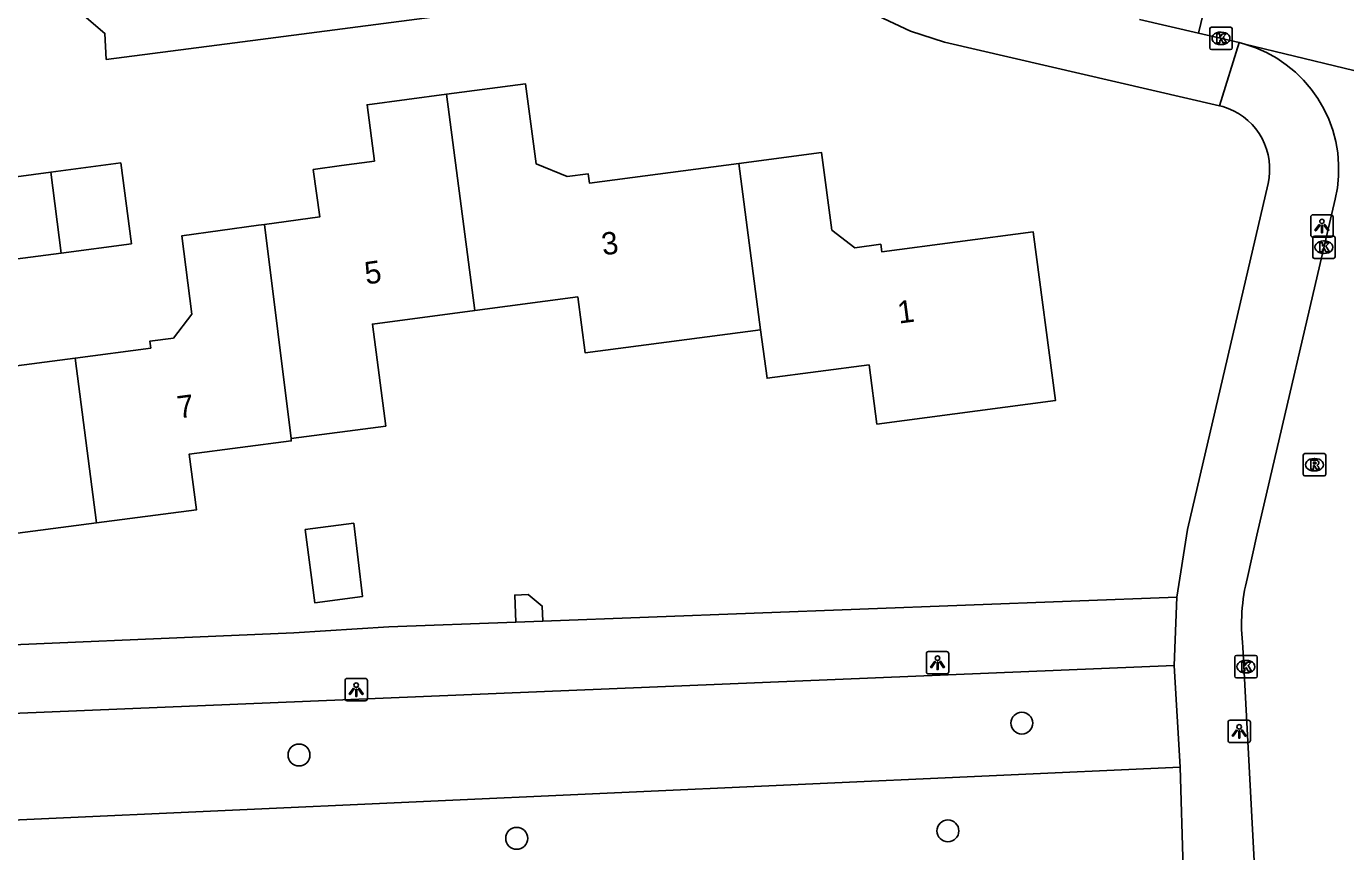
# Model space of a CAD drawing. Extents: x 161084 to 161928, y 385355 to 386522.
# Drawn here: x 161226.8 to 161285.7, y 385835.6 to 385872.4 of the extents above; entities that cross this region are included whole.
import ezdxf

# ---------------------------------------------------------------- set-up
doc = ezdxf.new("R2010")
doc.units = 0
for name, color, linetype in [('IMGEO_Boom', 7, 'Continuous'), ('IMGEO_Groenvoorziening', 7, 'Continuous'), ('IMGEO_Kolk', 7, 'Continuous'), ('IMGEO_Lichtpunt', 7, 'Continuous'), ('IMGEO_Muur', 7, 'Continuous'), ('IMGEO_Pand', 7, 'Continuous'), ('IMGEO_Pand_nummerreeks', 7, 'Continuous'), ('IMGEO_Rijbaan_lokaal_open', 7, 'Continuous'), ('IMGEO_Rioolput', 7, 'Continuous'), ('IMGEO_Voetpad_open', 7, 'Continuous')]:
    doc.layers.add(name, color=color, linetype=linetype)

msp = doc.modelspace()

# ---------------------------------------------------------------- linework, layer by layer
at = {"layer": 'IMGEO_Boom'}
for centre in [(161271.206, 385841.322), (161238.934, 385839.897), (161267.906, 385836.508), (161248.656, 385836.176)]:
    msp.add_circle(centre, 0.489, dxfattribs=at)
at = {"layer": 'IMGEO_Groenvoorziening'}
msp.add_lwpolyline([(161278.27, 385839.356), (161201.511, 385835.864)], dxfattribs=at)
at = {"layer": 'IMGEO_Kolk'}
for p, q in [((161279.596, 385871.471), (161279.596, 385872.323)), ((161279.671, 385872.397), (161280.523, 385872.397)), ((161280.084, 385872.177), (161280.109, 385872.177)), ((161280.597, 385872.323), (161280.597, 385871.471)), ((161280.107, 385871.617), (161280.082, 385871.617)), ((161280.523, 385871.397), (161279.671, 385871.397)), ((161284.191, 385862.145), (161284.191, 385862.997)), ((161284.266, 385863.071), (161285.118, 385863.071)), ((161284.679, 385862.851), (161284.704, 385862.851)), ((161285.192, 385862.997), (161285.192, 385862.145)), ((161284.702, 385862.291), (161284.677, 385862.291)), ((161285.118, 385862.071), (161284.266, 385862.071)), ((161280.711, 385843.415), (161280.711, 385844.267)), ((161280.786, 385844.341), (161281.638, 385844.341)), ((161281.199, 385844.121), (161281.224, 385844.121)), ((161281.712, 385844.267), (161281.712, 385843.415)), ((161281.638, 385843.341), (161280.786, 385843.341)), ((161281.222, 385843.561), (161281.197, 385843.561))]:
    msp.add_line(p, q, dxfattribs=at)
for points in [[(161279.596, 385871.471), (161279.596, 385872.323)], [(161279.671, 385872.397), (161280.523, 385872.397)], [(161280.597, 385872.323), (161280.597, 385871.471)], [(161279.917, 385872.097), (161280.04, 385872.097), (161280.04, 385871.946), (161280.17, 385872.097), (161280.334, 385872.097), (161280.188, 385871.946), (161280.341, 385871.697), (161280.189, 385871.697), (161280.104, 385871.861), (161280.04, 385871.794), (161280.04, 385871.697), (161279.917, 385871.697), (161279.917, 385872.097)], [(161280.523, 385871.397), (161279.671, 385871.397)], [(161284.191, 385862.145), (161284.191, 385862.997)], [(161284.266, 385863.071), (161285.118, 385863.071)], [(161284.512, 385862.771), (161284.635, 385862.771), (161284.635, 385862.62), (161284.765, 385862.771), (161284.929, 385862.771), (161284.783, 385862.62), (161284.936, 385862.371), (161284.784, 385862.371), (161284.699, 385862.535), (161284.635, 385862.468), (161284.635, 385862.371), (161284.512, 385862.371), (161284.512, 385862.771)], [(161285.192, 385862.997), (161285.192, 385862.145)], [(161285.118, 385862.071), (161284.266, 385862.071)], [(161280.711, 385843.415), (161280.711, 385844.267)], [(161280.786, 385844.341), (161281.638, 385844.341)], [(161281.032, 385844.041), (161281.155, 385844.041), (161281.155, 385843.89), (161281.285, 385844.041), (161281.449, 385844.041), (161281.303, 385843.89), (161281.456, 385843.641), (161281.304, 385843.641), (161281.219, 385843.805), (161281.155, 385843.738), (161281.155, 385843.641), (161281.032, 385843.641), (161281.032, 385844.041)], [(161281.712, 385844.267), (161281.712, 385843.415)], [(161281.638, 385843.341), (161280.786, 385843.341)]]:
    msp.add_lwpolyline(points, dxfattribs=at)
for centre, start, end in [((161279.673, 385872.321), 91.55205, 178.44795), ((161279.673, 385872.321), 91.55205, 178.44795), ((161280.521, 385872.321), 1.55205, 88.44795), ((161280.521, 385872.321), 1.55205, 88.44795), ((161279.673, 385871.473), 181.55205, 268.44795), ((161279.673, 385871.473), 181.55205, 268.44795), ((161280.521, 385871.473), 271.55205, 358.44795), ((161280.521, 385871.473), 271.55205, 358.44795), ((161284.268, 385862.995), 91.55205, 178.44795), ((161284.268, 385862.995), 91.55205, 178.44795), ((161285.116, 385862.995), 1.55205, 88.44795), ((161285.116, 385862.995), 1.55205, 88.44795), ((161284.268, 385862.147), 181.55205, 268.44795), ((161284.268, 385862.147), 181.55205, 268.44795), ((161285.116, 385862.147), 271.55205, 358.44795), ((161285.116, 385862.147), 271.55205, 358.44795), ((161280.788, 385844.265), 91.55205, 178.44795), ((161280.788, 385844.265), 91.55205, 178.44795), ((161281.636, 385844.265), 1.55205, 88.44795), ((161281.636, 385844.265), 1.55205, 88.44795), ((161280.788, 385843.417), 181.55205, 268.44795), ((161280.788, 385843.417), 181.55205, 268.44795), ((161281.636, 385843.417), 271.55205, 358.44795), ((161281.636, 385843.417), 271.55205, 358.44795)]:
    msp.add_arc(centre, 0.0765, start, end, dxfattribs=at)
for centre, major_axis, ratio, start_param, end_param in [((161280.083, 385871.897), (-0.387, 0.002), 0.722429, 4.712389, 7.853982), ((161280.108, 385871.897), (-0.39, 0.002), 0.717154, 1.570796, 4.712389), ((161284.678, 385862.571), (-0.387, 0.002), 0.722429, 4.712389, 7.853982), ((161284.703, 385862.571), (-0.39, 0.002), 0.717154, 1.570796, 4.712389), ((161281.198, 385843.841), (-0.387, 0.002), 0.722429, 4.712389, 7.853982), ((161281.223, 385843.841), (-0.39, 0.002), 0.717154, 1.570796, 4.712389)]:
    msp.add_ellipse(centre, major_axis=major_axis, ratio=ratio, start_param=start_param, end_param=end_param, dxfattribs=at)
at = {"layer": 'IMGEO_Lichtpunt'}
for p, q in [((161284.105, 385863.926), (161284.105, 385863.119)), ((161284.105, 385863.926), (161284.105, 385863.119)), ((161285.007, 385864.021), (161284.199, 385864.021)), ((161285.007, 385864.021), (161284.199, 385864.021)), ((161285.101, 385863.119), (161285.101, 385863.926)), ((161285.101, 385863.119), (161285.101, 385863.926)), ((161284.199, 385863.025), (161285.007, 385863.025)), ((161284.199, 385863.025), (161285.007, 385863.025)), ((161267.846, 385844.516), (161267.038, 385844.516)), ((161267.846, 385844.516), (161267.038, 385844.516)), ((161266.944, 385844.421), (161266.944, 385843.614)), ((161266.944, 385844.421), (161266.944, 385843.614)), ((161267.94, 385843.614), (161267.94, 385844.421)), ((161267.94, 385843.614), (161267.94, 385844.421)), ((161241.893, 385843.316), (161241.085, 385843.316)), ((161241.893, 385843.316), (161241.085, 385843.316)), ((161267.038, 385843.52), (161267.846, 385843.52)), ((161267.038, 385843.52), (161267.846, 385843.52)), ((161240.991, 385843.221), (161240.991, 385842.414)), ((161240.991, 385843.221), (161240.991, 385842.414)), ((161241.987, 385842.414), (161241.987, 385843.221)), ((161241.987, 385842.414), (161241.987, 385843.221)), ((161241.085, 385842.32), (161241.893, 385842.32)), ((161241.085, 385842.32), (161241.893, 385842.32)), ((161280.412, 385841.357), (161280.412, 385840.55)), ((161280.412, 385841.357), (161280.412, 385840.55)), ((161281.314, 385841.452), (161280.506, 385841.452)), ((161281.314, 385841.452), (161280.506, 385841.452)), ((161281.408, 385840.55), (161281.408, 385841.357)), ((161281.408, 385840.55), (161281.408, 385841.357)), ((161280.506, 385840.456), (161281.314, 385840.456)), ((161280.506, 385840.456), (161281.314, 385840.456))]:
    msp.add_line(p, q, dxfattribs=at)
for points in [[(161284.479, 385863.59), (161284.518, 385863.562), (161284.33, 385863.3), (161284.292, 385863.327), (161284.479, 385863.59)], [(161284.581, 385863.542), (161284.628, 385863.542), (161284.628, 385863.22), (161284.581, 385863.22), (161284.581, 385863.542)], [(161284.691, 385863.562), (161284.729, 385863.589), (161284.916, 385863.327), (161284.877, 385863.299), (161284.691, 385863.562)], [(161267.318, 385844.085), (161267.357, 385844.057), (161267.169, 385843.795), (161267.131, 385843.822), (161267.318, 385844.085)], [(161267.42, 385844.037), (161267.467, 385844.037), (161267.467, 385843.715), (161267.42, 385843.715), (161267.42, 385844.037)], [(161267.53, 385844.057), (161267.568, 385844.084), (161267.755, 385843.822), (161267.716, 385843.794), (161267.53, 385844.057)], [(161241.365, 385842.885), (161241.404, 385842.857), (161241.216, 385842.595), (161241.178, 385842.622), (161241.365, 385842.885)], [(161241.467, 385842.837), (161241.514, 385842.837), (161241.514, 385842.515), (161241.467, 385842.515), (161241.467, 385842.837)], [(161241.577, 385842.857), (161241.615, 385842.884), (161241.802, 385842.622), (161241.763, 385842.594), (161241.577, 385842.857)], [(161280.786, 385841.021), (161280.825, 385840.993), (161280.637, 385840.731), (161280.599, 385840.758), (161280.786, 385841.021)], [(161280.888, 385840.973), (161280.935, 385840.973), (161280.935, 385840.651), (161280.888, 385840.651), (161280.888, 385840.973)], [(161280.998, 385840.993), (161281.036, 385841.02), (161281.223, 385840.758), (161281.184, 385840.73), (161280.998, 385840.993)]]:
    msp.add_lwpolyline(points, dxfattribs=at)
for centre in [(161284.604, 385863.724), (161267.443, 385844.219), (161241.49, 385843.019), (161280.911, 385841.155)]:
    msp.add_circle(centre, 0.0994, dxfattribs=at)
for centre, start, end in [((161284.199, 385863.926), 90, 180), ((161284.199, 385863.926), 90, 180), ((161285.007, 385863.926), 0, 90), ((161285.007, 385863.926), 0, 90), ((161284.199, 385863.119), 180, 270), ((161284.199, 385863.119), 180, 270), ((161285.007, 385863.119), 270, 0), ((161285.007, 385863.119), 270, 360), ((161267.038, 385844.421), 90, 180), ((161267.038, 385844.421), 90, 180), ((161267.846, 385844.421), 0, 90), ((161267.846, 385844.421), 0, 90), ((161241.085, 385843.221), 90, 180), ((161241.085, 385843.221), 90, 180), ((161241.893, 385843.221), 0, 90), ((161241.893, 385843.221), 0, 90), ((161267.038, 385843.614), 180, 270), ((161267.038, 385843.614), 180, 270), ((161267.846, 385843.614), 270, 0), ((161267.846, 385843.614), 270, 360), ((161241.085, 385842.414), 180, 270), ((161241.085, 385842.414), 180, 270), ((161241.893, 385842.414), 270, 0), ((161241.893, 385842.414), 270, 360), ((161280.506, 385841.357), 90, 180), ((161280.506, 385841.357), 90, 180), ((161281.314, 385841.357), 0, 90), ((161281.314, 385841.357), 0, 90), ((161280.506, 385840.55), 180, 270), ((161280.506, 385840.55), 180, 270), ((161281.314, 385840.55), 270, 0), ((161281.314, 385840.55), 270, 360)]:
    msp.add_arc(centre, 0.0946, start, end, dxfattribs=at)
at = {"layer": 'IMGEO_Muur'}
msp.add_lwpolyline([(161221.978, 385844.639), (161238.698, 385845.353)], dxfattribs=at)
at = {"layer": 'IMGEO_Pand'}
for points in [[(161245.515, 385869.401), (161249.053, 385869.865), (161249.522, 385866.295), (161250.901, 385865.723), (161251.85, 385865.848), (161251.904, 385865.435), (161258.571, 385866.31)], [(161237.391, 385863.585), (161239.867, 385863.929), (161239.573, 385866.041), (161240.829, 385866.216), (161242.304, 385866.421), (161241.974, 385868.936), (161245.515, 385869.401)], [(161246.783, 385859.743), (161245.515, 385869.401)], [(161227.852, 385865.917), (161230.975, 385866.333), (161231.455, 385862.73), (161228.324, 385862.312)], [(161258.571, 385866.31), (161262.264, 385866.795), (161262.717, 385863.339), (161263.747, 385862.549), (161264.906, 385862.701), (161264.95, 385862.366), (161271.714, 385863.254), (161272.703, 385855.722), (161264.737, 385854.676), (161264.39, 385857.318), (161259.83, 385856.72), (161259.546, 385858.888)], [(161258.571, 385866.31), (161259.546, 385858.888)], [(161228.324, 385862.312), (161225.225, 385861.899), (161224.745, 385865.503), (161227.852, 385865.917)], [(161227.852, 385865.917), (161228.324, 385862.312)], [(161228.937, 385857.624), (161232.315, 385858.066), (161232.275, 385858.37), (161233.326, 385858.507), (161234.157, 385859.589), (161233.7, 385863.073), (161237.127, 385863.549), (161237.391, 385863.585)], [(161237.391, 385863.585), (161238.582, 385854.024)], [(161221.009, 385863.091), (161222.837, 385861.686), (161223.314, 385858.05), (161224.555, 385857.323), (161225.612, 385857.462), (161225.647, 385857.193), (161228.937, 385857.624)], [(161229.9, 385850.261), (161225.446, 385849.678), (161225.133, 385852.065), (161220.426, 385851.449), (161219.208, 385860.75)], [(161259.546, 385858.888), (161251.711, 385857.859), (161251.384, 385860.349), (161246.783, 385859.743)], [(161246.783, 385859.743), (161242.212, 385859.142), (161242.812, 385854.581), (161238.582, 385854.024)], [(161228.937, 385857.624), (161229.9, 385850.261)], [(161238.582, 385854.024), (161238.593, 385853.925), (161234.031, 385853.328), (161234.356, 385850.844), (161229.9, 385850.261)], [(161241.385, 385850.243), (161241.764, 385846.968), (161239.637, 385846.694), (161239.215, 385849.963), (161241.385, 385850.243)], [(161248.611, 385845.826), (161248.565, 385847.041), (161249.162, 385847.064), (161249.795, 385846.545), (161249.82, 385845.874)], [(161248.611, 385845.826), (161249.82, 385845.874)]]:
    msp.add_lwpolyline(points, dxfattribs=at)
at = {"layer": 'IMGEO_Rijbaan_lokaal_open'}
for points in [[(161259.346, 385874.464), (161257.475, 385874.49), (161236.064, 385871.703), (161230.331, 385870.957), (161230.27, 385872.118), (161227.681, 385874.351), (161226.449, 385874.167), (161226.437, 385874.268), (161225.75, 385879.929)], [(161280.685, 385878.758), (161279.098, 385872.13)], [(161279.098, 385872.13), (161276.452, 385872.742)], [(161280.909, 385871.711), (161279.098, 385872.13)], [(161281.16, 385871.644), (161280.909, 385871.711)], [(161281.275, 385847.826), (161281.693, 385849.708), (161285.193, 385864.712), (161285.291, 385865.223), (161285.342, 385865.741), (161285.347, 385866.261), (161285.306, 385866.78), (161285.218, 385867.293), (161285.085, 385867.796), (161284.908, 385868.285), (161284.687, 385868.756), (161284.425, 385869.206), (161284.125, 385869.63), (161283.787, 385870.026), (161283.416, 385870.391), (161283.013, 385870.72), (161282.583, 385871.013), (161282.128, 385871.265), (161281.652, 385871.476), (161281.16, 385871.644)], [(161281.16, 385871.644), (161298.896, 385867.349), (161299.018, 385867.307)], [(161283.529, 385797.49), (161282.021, 385826.764), (161281.072, 385844.719)]]:
    msp.add_lwpolyline(points, dxfattribs=at)
msp.add_arc((161289.734, 385845.713), 8.718, 165.97566, 186.54797, dxfattribs=at)
at = {"layer": 'IMGEO_Rioolput'}
for p, q in [((161283.77, 385852.433), (161283.77, 385853.285)), ((161283.845, 385853.359), (161284.697, 385853.359)), ((161284.771, 385853.285), (161284.771, 385852.433)), ((161284.258, 385853.139), (161284.283, 385853.139)), ((161284.697, 385852.359), (161283.845, 385852.359)), ((161284.281, 385852.579), (161284.256, 385852.579))]:
    msp.add_line(p, q, dxfattribs=at)
for points in [[(161283.77, 385852.433), (161283.77, 385853.285)], [(161283.845, 385853.359), (161284.697, 385853.359)], [(161284.771, 385853.285), (161284.771, 385852.433)], [(161284.359, 385853.057), (161284.107, 385853.059), (161284.107, 385852.659)], [(161284.107, 385852.659), (161284.231, 385852.659), (161284.231, 385852.821), (161284.242, 385852.821)], [(161284.285, 385852.978), (161284.231, 385852.978), (161284.231, 385852.897)], [(161284.231, 385852.897), (161284.283, 385852.897)], [(161284.289, 385852.792), (161284.36, 385852.659), (161284.5, 385852.659), (161284.435, 385852.785)], [(161284.697, 385852.359), (161283.845, 385852.359)]]:
    msp.add_lwpolyline(points, dxfattribs=at)
for centre, radius, start, end in [((161283.847, 385853.283), 0.0765, 91.55205, 178.44795), ((161283.847, 385853.283), 0.0765, 91.55205, 178.44795), ((161284.695, 385853.283), 0.0765, 1.55205, 88.44795), ((161284.695, 385853.283), 0.0765, 1.55205, 88.44795), ((161284.241, 385852.768), 0.0533, 26.02933, 88.69889), ((161284.267, 385853.086), 0.19, 274.7715, 282.96867), ((161284.291, 385852.882), 0.0964, 77.00612, 93.18647), ((161284.305, 385852.939), 0.0378, 276.66336, 79.67722), ((161284.358, 385852.947), 0.109, 350.36119, 89.41601), ((161284.356, 385852.947), 0.112, 277.58423, 350.98172), ((161284.34, 385852.732), 0.108, 29.51342, 73.79051), ((161283.847, 385852.435), 0.0765, 181.55205, 268.44795), ((161283.847, 385852.435), 0.0765, 181.55205, 268.44795), ((161284.695, 385852.435), 0.0765, 271.55205, 358.44795), ((161284.695, 385852.435), 0.0765, 271.55205, 358.44795)]:
    msp.add_arc(centre, radius, start, end, dxfattribs=at)
for centre, major_axis, ratio, start_param, end_param in [((161284.257, 385852.859), (-0.387, 0.002), 0.722429, 4.712389, 7.853982), ((161284.282, 385852.859), (-0.39, 0.002), 0.717154, 1.570796, 4.712389)]:
    msp.add_ellipse(centre, major_axis=major_axis, ratio=ratio, start_param=start_param, end_param=end_param, dxfattribs=at)
at = {"layer": 'IMGEO_Voetpad_open'}
for points in [[(161280.03, 385868.89), (161267.756, 385871.733), (161266.234, 385872.223), (161264.784, 385872.899), (161263.633, 385873.435), (161262.438, 385873.867), (161261.21, 385874.19), (161259.958, 385874.402), (161259.346, 385874.464)], [(161280.909, 385871.711), (161280.03, 385868.89)], [(161278.123, 385846.938), (161278.603, 385849.97), (161282.197, 385865.412), (161282.244, 385865.667), (161282.269, 385865.925), (161282.27, 385866.184), (161282.248, 385866.442), (161282.203, 385866.697), (161282.136, 385866.947), (161282.046, 385867.19), (161281.935, 385867.424), (161281.804, 385867.647), (161281.653, 385867.858), (161281.484, 385868.054), (161281.298, 385868.235), (161281.097, 385868.398), (161280.882, 385868.542), (161280.655, 385868.667), (161280.417, 385868.771), (161280.172, 385868.853), (161280.03, 385868.89)], [(161249.82, 385845.874), (161278.123, 385846.938)], [(161278.123, 385846.938), (161278.01, 385843.892)], [(161200.484, 385843.768), (161219.637, 385844.57), (161219.613, 385845.125), (161220.136, 385846.126), (161221.198, 385846.171), (161221.942, 385845.487), (161221.978, 385844.639), (161238.698, 385845.353), (161242.95, 385845.616), (161248.611, 385845.826)], [(161278.01, 385843.892), (161200.876, 385840.705)], [(161278.01, 385843.892), (161278.27, 385839.356)], [(161278.27, 385839.356), (161278.406, 385834.825)]]:
    msp.add_lwpolyline(points, dxfattribs=at)

# ---------------------------------------------------------------- texts
at = {"layer": 'IMGEO_Pand_nummerreeks'}
for s, rotation, p in [('3', 7.47776, (161252.507, 385862.206)), ('5', 7.90682, (161241.934, 385860.905)), ('1', 7.4792, (161265.719, 385859.158)), ('7', 7.45991, (161233.562, 385854.921))]:
    msp.add_text(s, height=1, rotation=rotation, dxfattribs=at).set_placement(p)

doc.saveas('drawing.dxf')
